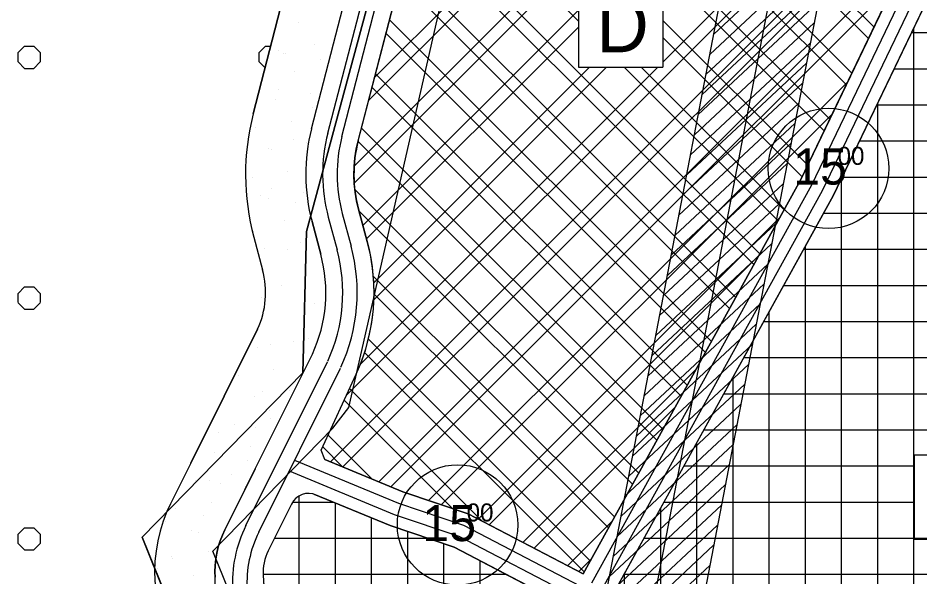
# Model space of a CAD drawing. Extents: x 419109 to 421295, y 4452223 to 4457798.
# Drawn here: x 419705 to 420079.2, y 4455575.7 to 4455807.8 of the extents above; entities that cross this region are included whole.
import ezdxf

# ---------------------------------------------------------------- set-up
doc = ezdxf.new("R2010")
doc.units = 0
for name, color, linetype in [('ADA', 7, 'Continuous'), ('ADAKENARI', 7, 'Continuous'), ('KALDIRIM_FAT', 7, 'Continuous'), ('KD_DAIRE', 7, 'Continuous'), ('KD_YGEN', 7, 'Continuous'), ('PL_AYA_PARK_DINLENME', 7, 'Continuous'), ('PL_K_DEPOLAMA', 7, 'Continuous'), ('PL_KA_TARIM_ALANI', 7, 'Continuous'), ('PL_TİCARET', 7, 'Continuous'), ('SEMBOL_FAT', 7, 'Continuous'), ('TA_ENH_154', 7, 'Continuous'), ('TA_ENH_KORUMA', 7, 'Continuous'), ('TA_ENH_TARAMA', 7, 'Continuous'), ('TR_TARIMALANI', 7, 'Continuous'), ('TRFAT_DEPOLAMA', 7, 'Continuous'), ('TRFAT_PARKALANI', 7, 'Continuous'), ('TRFAT_TİCARET', 7, 'Continuous')]:
    doc.layers.add(name, color=color, linetype=linetype)

msp = doc.modelspace()

# ---------------------------------------------------------------- linework, layer by layer
at = {"layer": 'ADA'}
for p, q in [((419756.46, 4455592.19), (419823.13, 4455660.45)), ((419783.44, 4455525.52), (419756.46, 4455592.19))]:
    msp.add_line(p, q, dxfattribs=at)
at = {"layer": 'ADAKENARI'}
for p, q in [((419802.57, 4455768.04), (419857.93, 4455982.18)), ((419826.78, 4455761.78), (419882.14, 4455975.93)), ((419846.14, 4455756.78), (419902.93, 4455976.43)), ((420043.17, 4455733.9), (420134.21, 4455923.79)), ((420029.83, 4455740.78), (420113.83, 4455915.99)), ((419939.44, 4455577), (420029.83, 4455740.78)), ((419945.46, 4455556.86), (420043.17, 4455733.9)), ((419846.28, 4455728.45), (419849.92, 4455714.93)), ((419826.97, 4455723.26), (419830.61, 4455709.74)), ((419802.83, 4455716.76), (419806.46, 4455703.24)), ((419776.71, 4455623), (419804.4, 4455678.61)), ((419803.43, 4455620.54), (419827.12, 4455668.19)), ((419830.81, 4455628.27), (419845.3, 4455659.85)), ((419832.33, 4455624.4), (419830.81, 4455628.27)), ((419776.71, 4455623), (419768.21, 4455605.99)), ((419832.33, 4455624.4), (419864.61, 4455611.04)), ((419803.43, 4455620.54), (419799.07, 4455611.82)), ((419799.07, 4455611.82), (419790.75, 4455595.18)), ((419864.61, 4455611.04), (419891.81, 4455601.83)), ((419819.29, 4455607.23), (419818.5, 4455605.96)), ((419820.3, 4455608.33), (419819.29, 4455607.23)), ((419821.51, 4455609.22), (419820.3, 4455608.33)), ((419822.85, 4455609.88), (419821.51, 4455609.22)), ((419824.3, 4455610.27), (419822.85, 4455609.88)), ((419825.79, 4455610.38), (419824.3, 4455610.27)), ((419827.28, 4455610.21), (419825.79, 4455610.38)), ((419827.67, 4455610.1), (419827.28, 4455610.21)), ((419827.67, 4455610.1), (419859.33, 4455596.99)), ((419768.21, 4455605.99), (419766.74, 4455602.8)), ((419818.5, 4455605.96), (419808.79, 4455586.53)), ((419766.74, 4455602.8), (419765.22, 4455598.83)), ((419891.81, 4455601.83), (419939.44, 4455577)), ((419765.22, 4455598.83), (419763.96, 4455594.76)), ((419859.33, 4455596.99), (419885.9, 4455587.99)), ((419763.96, 4455594.76), (419762.97, 4455590.63)), ((419789.8, 4455593.1), (419788.86, 4455590.66)), ((419790.75, 4455595.18), (419789.8, 4455593.1)), ((419762.97, 4455590.63), (419762.26, 4455586.44)), ((419762.84, 4455589.82), (419762.4, 4455587.24)), ((419788.86, 4455590.66), (419788.09, 4455588.16)), ((419762.26, 4455586.44), (419761.82, 4455582.21)), ((419787.48, 4455585.61), (419787.04, 4455583.03)), ((419788.09, 4455588.16), (419787.48, 4455585.61)), ((419808.24, 4455585.34), (419807.77, 4455584.12)), ((419808.79, 4455586.53), (419808.24, 4455585.34)), ((419885.9, 4455587.99), (419940.17, 4455559.7)), ((419761.82, 4455582.21), (419761.65, 4455577.95)), ((419787.04, 4455583.03), (419786.77, 4455580.43)), ((419807.08, 4455581.6), (419806.86, 4455580.31)), ((419807.39, 4455582.87), (419807.08, 4455581.6)), ((419807.77, 4455584.12), (419807.39, 4455582.87)), ((419761.65, 4455577.95), (419761.75, 4455574.44)), ((419786.77, 4455580.43), (419786.67, 4455577.82)), ((419786.67, 4455577.82), (419786.73, 4455575.53)), ((419806.73, 4455579.01), (419806.68, 4455577.7)), ((419806.68, 4455577.7), (419806.71, 4455576.4)), ((419806.86, 4455580.31), (419806.73, 4455579.01)), ((419806.71, 4455576.4), (419815.93, 4455422.24))]:
    msp.add_line(p, q, dxfattribs=at)
for centre, radius, start, end in [((419899.91, 4455742.88), 100.53, 165.5054, 195.0581), ((419899.91, 4455742.88), 75.53, 165.5054, 195.0581), ((419899.91, 4455742.88), 55.53, 165.5054, 195.0581), ((419771.33, 4455693.79), 81.39, 335.3525, 15.0581), ((419771.33, 4455693.79), 61.39, 335.3525, 15.0581), ((419771.33, 4455693.79), 36.39, 335.3525, 15.0581)]:
    msp.add_arc(centre, radius, start, end, dxfattribs=at)
at = {"layer": 'KALDIRIM_FAT'}
for p, q in [((419833.56, 4455760.03), (419888.92, 4455974.18)), ((419839.36, 4455758.53), (419894.72, 4455972.67)), ((420034.28, 4455738.49), (420119.46, 4455916.16)), ((420038.73, 4455736.19), (420123.97, 4455914)), ((419943.11, 4455573.29), (420034.28, 4455738.49)), ((419947.48, 4455570.88), (420038.73, 4455736.19)), ((419833.73, 4455725.07), (419837.36, 4455711.56)), ((419839.52, 4455726.63), (419843.16, 4455713.11)), ((419799.53, 4455596.98), (419833.39, 4455665.07)), ((419804.9, 4455594.31), (419838.76, 4455662.4)), ((419819.76, 4455624.19), (419862.85, 4455606.36)), ((419817.53, 4455619.7), (419861.09, 4455601.68)), ((419862.85, 4455606.36), (419889.84, 4455597.22)), ((419861.09, 4455601.68), (419887.87, 4455592.6)), ((419889.84, 4455597.22), (419938.43, 4455571.88)), ((419887.87, 4455592.6), (419936.12, 4455567.45))]:
    msp.add_line(p, q, dxfattribs=at)
for centre, radius, start, end in [((419899.91, 4455742.88), 68.53, 165.5054, 195.0581), ((419899.91, 4455742.88), 62.53, 165.5054, 195.0581), ((419771.33, 4455693.79), 74.39, 335.3525, 15.0581), ((419771.33, 4455693.79), 68.39, 335.3525, 15.0581), ((419847.11, 4455573.32), 53.14, 153.5603, 183.4213), ((419847.11, 4455573.32), 47.14, 153.5603, 183.4213)]:
    msp.add_arc(centre, radius, start, end, dxfattribs=at)
at = {"layer": 'KD_DAIRE'}
for centre in [(420041.27, 4455745.36), (419887.38, 4455597.27)]:
    msp.add_circle(centre, 25, dxfattribs=at)
at = {"layer": 'PL_AYA_PARK_DINLENME'}
for p, q in [((419857.93, 4455982.18), (419802.57, 4455768.04)), ((419826.78, 4455761.78), (419882.14, 4455975.93)), ((419830.6, 4455709.74), (419826.97, 4455723.26)), ((419802.83, 4455716.76), (419806.46, 4455703.24)), ((419806.46, 4455703.24), (419806.46, 4455703.24))]:
    msp.add_line(p, q, dxfattribs=at)
for points in [[(420016.8, 4456927.25), (420013.63, 4456854.22), (420021.56, 4456763.74), (419972.35, 4456528.79), (419896.15, 4456444.66), (419851.71, 4456390.68), (419781.86, 4456219.24), (419743.76, 4456181.14), (419715.18, 4456046.21), (419900.92, 4456001.76), (419824.72, 4455719.19), (419823.13, 4455660.45), (419756.46, 4455592.19), (419783.44, 4455525.52), (419794.56, 4455425.51), (419778.68, 4455323.91)], [(419804.18, 4455325.18), (419819.77, 4455424.95), (419807.91, 4455531.7), (419785.76, 4455586.42), (419835.59, 4455637.43), (419842.19, 4455646.09), (419927.54, 4456021.09), (419744.69, 4456064.85), (419766.68, 4456168.71), (419803.1, 4456205.13), (419873.42, 4456377.73), (419915.08, 4456428.31), (419995.43, 4456517.04), (420046.79, 4456762.24), (420038.67, 4456854.78), (420041.73, 4456924.97)], [(419804.4, 4455678.61), (419776.71, 4455623), (419768.21, 4455605.99), (419766.74, 4455602.8), (419765.22, 4455598.83), (419763.96, 4455594.76), (419762.97, 4455590.63), (419762.84, 4455589.82), (419762.4, 4455587.24), (419762.26, 4455586.44), (419761.82, 4455582.21), (419761.65, 4455577.95), (419761.75, 4455574.44), (419762.54, 4455561.28), (419771.07, 4455418.55), (419772.93, 4455400.8), (419770.22, 4455288.15), (419798.46, 4455144.95), (419791.07, 4455126.52), (419788.42, 4455109.34), (419786.36, 4455074.3), (419779.83, 4455031.69), (419779.71, 4455015.11)], [(419795.28, 4455290.29), (419797.57, 4455385.64), (419797.88, 4455390.78), (419798.11, 4455400.41), (419795.99, 4455420.6), (419787.49, 4455562.77), (419786.85, 4455573.45), (419786.73, 4455575.53), (419786.67, 4455577.82), (419786.77, 4455580.43), (419787.04, 4455583.03), (419787.48, 4455585.61), (419788.09, 4455588.16), (419788.86, 4455590.66), (419789.8, 4455593.1), (419790.75, 4455595.18), (419799.07, 4455611.82), (419803.43, 4455620.54), (419827.12, 4455668.19)]]:
    msp.add_lwpolyline(points, dxfattribs=at)
for centre, radius, start, end in [((419899.91, 4455742.88), 100.53, 165.5054, 195.0581), ((419899.91, 4455742.88), 75.53, 165.5054, 195.0581), ((419771.33, 4455693.79), 61.39, 335.3525, 15.0581), ((419771.33, 4455693.79), 36.39, 335.3525, 15.0573), ((419771.33, 4455693.79), 36.39, 15.0575, 15.0581)]:
    msp.add_arc(centre, radius, start, end, dxfattribs=at)
at = {"layer": 'PL_K_DEPOLAMA'}
msp.add_lwpolyline([(420113.83, 4455915.99), (420029.83, 4455740.78), (419939.44, 4455577), (419891.81, 4455601.83), (419864.61, 4455611.04), (419832.33, 4455624.4), (419830.81, 4455628.27), (419845.3, 4455659.85), (419847.47, 4455665.05), (419849.28, 4455670.39), (419850.71, 4455675.85), (419851.76, 4455681.39), (419852.43, 4455686.99), (419852.7, 4455692.62), (419852.59, 4455698.26), (419852.09, 4455703.87), (419851.19, 4455709.44), (419849.92, 4455714.93), (419846.28, 4455728.45), (419845.46, 4455731.94), (419844.87, 4455735.47), (419844.51, 4455739.03), (419844.38, 4455742.61), (419844.47, 4455746.18), (419844.8, 4455749.75), (419845.36, 4455753.28), (419846.14, 4455756.78), (419846.14, 4455756.78), (419902.93, 4455976.43)], dxfattribs=at)
at = {"layer": 'PL_KA_TARIM_ALANI'}
msp.add_lwpolyline([(419792.54, 4455014.98), (419819.96, 4455165.16), (419778.68, 4455323.91), (419794.56, 4455425.51), (419783.44, 4455525.52), (419756.46, 4455592.19), (419823.13, 4455660.45), (419824.72, 4455719.19), (419900.92, 4456001.76), (419869.84, 4456009.19), (419715.18, 4456046.21), (419743.76, 4456181.14), (419781.86, 4456219.24), (419851.71, 4456390.68), (419896.15, 4456444.66), (419972.35, 4456528.79), (420021.56, 4456763.74), (420013.63, 4456854.22), (420016.8, 4456927.25), (420027.91, 4457006.62), (420158.52, 4456994.43), (420142.12, 4457086.4)], dxfattribs=at)
at = {"layer": 'PL_TİCARET'}
for points in [[(420153.07, 4455976.48), (420152.11, 4455974.16), (420151.45, 4455961.22), (420137.18, 4455930.24), (420134.21, 4455923.79), (420043.17, 4455733.9), (419945.46, 4455556.86), (419940.17, 4455559.7)], [(419940.17, 4455559.7), (419885.9, 4455587.99), (419859.33, 4455596.99), (419827.67, 4455610.1), (419827.28, 4455610.21), (419825.79, 4455610.38), (419824.3, 4455610.27), (419822.85, 4455609.88), (419821.51, 4455609.22), (419820.3, 4455608.33), (419819.29, 4455607.23), (419818.5, 4455605.96), (419808.79, 4455586.53), (419808.24, 4455585.34), (419807.77, 4455584.12), (419807.39, 4455582.87), (419807.08, 4455581.6), (419806.86, 4455580.31), (419806.73, 4455579.01), (419806.68, 4455577.7), (419806.71, 4455576.4), (419815.93, 4455422.24)]]:
    msp.add_lwpolyline(points, dxfattribs=at)
at = {"layer": 'SEMBOL_FAT'}
for p, q in [((419937.51, 4455822.43), (419937.51, 4455787.43)), ((419972.51, 4455822.43), (419972.51, 4455787.43)), ((419937.51, 4455787.43), (419972.51, 4455787.43)), ((420076.85, 4455626.43), (420076.85, 4455591.43)), ((420076.85, 4455626.43), (420111.85, 4455626.43)), ((420076.85, 4455591.43), (420111.85, 4455591.43))]:
    msp.add_line(p, q, dxfattribs=at)
at = {"layer": 'TA_ENH_154'}
msp.add_lwpolyline([(419862.83, 4455014.24), (420170.14, 4456613.6), (420230.68, 4456928.68), (420176.89, 4457440.84), (420133.44, 4457787.81)], dxfattribs=at)
at = {"layer": 'TA_ENH_KORUMA'}
msp.add_line((419842.5, 4455014.45), (420150.5, 4456617.38), dxfattribs=at)
msp.add_lwpolyline([(420153.62, 4457787.6), (420196.76, 4457443.12), (420250.88, 4456927.82), (420189.78, 4456609.83), (419883.15, 4455014.02)], dxfattribs=at)
at = {"layer": 'TA_ENH_TARAMA'}
for p, q in [((419993.64, 4455801.05), (420043.29, 4455847.45)), ((419992.04, 4455792.71), (420041.69, 4455839.11)), ((419990.43, 4455784.37), (420040.08, 4455830.77)), ((419988.83, 4455776.02), (420038.48, 4455822.42)), ((419987.23, 4455767.68), (420036.88, 4455814.08)), ((419985.62, 4455759.34), (420035.28, 4455805.74)), ((419984.02, 4455751), (420033.67, 4455797.4)), ((419982.42, 4455742.65), (420032.07, 4455789.06)), ((419980.82, 4455734.31), (420030.47, 4455780.71)), ((419979.21, 4455725.97), (420028.86, 4455772.37)), ((419977.61, 4455717.63), (420027.26, 4455764.03)), ((419976.01, 4455709.28), (420025.66, 4455755.69)), ((419974.4, 4455700.94), (420024.06, 4455747.34)), ((419972.8, 4455692.6), (420022.45, 4455739)), ((419971.2, 4455684.26), (420020.85, 4455730.66)), ((419969.59, 4455675.92), (420019.25, 4455722.32)), ((419967.99, 4455667.57), (420017.64, 4455713.98)), ((419966.39, 4455659.23), (420016.04, 4455705.63)), ((419964.79, 4455650.89), (420014.44, 4455697.29)), ((419963.18, 4455642.55), (420012.83, 4455688.95)), ((419961.58, 4455634.2), (420011.23, 4455680.61)), ((419959.98, 4455625.86), (420009.63, 4455672.26)), ((419958.37, 4455617.52), (420008.03, 4455663.92)), ((419956.77, 4455609.18), (420006.42, 4455655.58)), ((419955.17, 4455600.84), (420004.82, 4455647.24)), ((419953.57, 4455592.49), (420003.22, 4455638.9)), ((419951.96, 4455584.15), (420001.61, 4455630.55)), ((419950.36, 4455575.81), (420000.01, 4455622.21)), ((419948.76, 4455567.47), (419998.41, 4455613.87)), ((419947.15, 4455559.12), (419996.81, 4455605.53)), ((419945.55, 4455550.78), (419995.2, 4455597.18)), ((419943.95, 4455542.44), (419993.6, 4455588.84)), ((419942.35, 4455534.1), (419992, 4455580.5))]:
    msp.add_line(p, q, dxfattribs=at)
at = {"layer": 'TR_TARIMALANI'}
for p, q in [((419705, 4455793.42), (419707.71, 4455796.13)), ((419707.75, 4455796.14), (419711.58, 4455796.14)), ((419714.25, 4455793.42), (419711.54, 4455796.13)), ((419805, 4455793.42), (419807.71, 4455796.13)), ((419807.74, 4455796.14), (419809.84, 4455796.14)), ((419705.04, 4455789.6), (419705.04, 4455793.43)), ((419714.29, 4455789.6), (419714.29, 4455793.43)), ((419805.03, 4455789.6), (419805.03, 4455793.43)), ((419707.71, 4455786.88), (419705, 4455789.59)), ((419707.75, 4455786.89), (419711.58, 4455786.89)), ((419711.54, 4455786.88), (419714.25, 4455789.59)), ((419807.5, 4455787.09), (419805, 4455789.59)), ((419705, 4455693.42), (419707.71, 4455696.13)), ((419705.04, 4455689.6), (419705.04, 4455693.43)), ((419707.75, 4455696.14), (419711.58, 4455696.14)), ((419714.25, 4455693.42), (419711.54, 4455696.13)), ((419714.29, 4455689.6), (419714.29, 4455693.43)), ((419707.71, 4455686.88), (419705, 4455689.59)), ((419711.54, 4455686.88), (419714.25, 4455689.59)), ((419707.75, 4455686.89), (419711.58, 4455686.89)), ((419705, 4455593.42), (419707.71, 4455596.13)), ((419707.75, 4455596.14), (419711.58, 4455596.14)), ((419714.25, 4455593.42), (419711.54, 4455596.13)), ((419705.04, 4455589.6), (419705.04, 4455593.43)), ((419714.29, 4455589.6), (419714.29, 4455593.43)), ((419707.71, 4455586.88), (419705, 4455589.59)), ((419711.54, 4455586.88), (419714.25, 4455589.59)), ((419707.75, 4455586.89), (419711.58, 4455586.89))]:
    msp.add_line(p, q, dxfattribs=at)
at = {"layer": 'TRFAT_DEPOLAMA'}
for p, q in [((419899.81, 4455964.36), (420060.15, 4455804.01)), ((419898.35, 4455958.74), (420057.86, 4455799.23)), ((419850.47, 4455773.54), (420028.3, 4455951.36)), ((419852.94, 4455783.07), (420023.29, 4455953.43)), ((419844.49, 4455746.34), (420043.3, 4455945.15)), ((419844.5, 4455739.28), (420048.31, 4455943.08)), ((419894, 4455941.88), (420050.99, 4455784.89)), ((419892.54, 4455936.27), (420048.69, 4455780.11)), ((419841.38, 4455651.3), (420108.34, 4455918.26)), ((419888.19, 4455919.41), (420041.82, 4455765.78)), ((419972.51, 4455789.51), (420103.33, 4455920.33)), ((419886.73, 4455913.79), (420039.53, 4455761)), ((419834.7, 4455623.42), (420101.45, 4455890.16)), ((419839.71, 4455621.35), (420094.94, 4455876.58)), ((419875.11, 4455868.84), (419937.51, 4455806.44)), ((419870.76, 4455851.99), (420012.81, 4455709.93)), ((419869.3, 4455846.37), (420010.3, 4455705.38)), ((419854.71, 4455615.14), (420075.41, 4455835.83)), ((419864.95, 4455829.51), (420002.75, 4455691.71)), ((419859.71, 4455613.07), (420068.89, 4455822.25)), ((419863.49, 4455823.89), (420000.24, 4455687.15)), ((419848.11, 4455721.67), (419937.51, 4455811.08)), ((419859.14, 4455807.04), (419992.69, 4455673.48)), ((419972.51, 4455806.8), (420032.65, 4455746.66)), ((419849.6, 4455716.1), (419937.51, 4455804.01)), ((419857.68, 4455801.42), (419990.18, 4455668.93)), ((419972.51, 4455799.73), (420030.36, 4455741.88)), ((419847.05, 4455664.05), (419970.43, 4455787.43)), ((419852.6, 4455697.88), (419942.15, 4455787.43)), ((419852.62, 4455690.83), (419949.22, 4455787.43)), ((419956.53, 4455787.43), (420020.36, 4455723.6)), ((419963.6, 4455787.43), (420022.87, 4455728.16)), ((419853.33, 4455784.56), (419982.63, 4455655.26)), ((419875.28, 4455607.43), (420049.36, 4455781.5)), ((419851.87, 4455778.95), (419980.12, 4455650.7)), ((419880.57, 4455605.64), (420042.85, 4455767.92)), ((419847.52, 4455762.09), (419972.57, 4455637.03)), ((419846.07, 4455756.46), (419970.06, 4455632.47)), ((419844.76, 4455736.56), (419962.52, 4455618.81)), ((419846.46, 4455727.79), (419960, 4455614.25)), ((419895.86, 4455599.72), (420021.11, 4455724.97)), ((419900.51, 4455597.29), (420012.4, 4455709.19)), ((419852.37, 4455700.66), (419952.46, 4455600.58)), ((419852.69, 4455693.28), (419949.94, 4455596.02)), ((419850.34, 4455674.42), (419942.4, 4455582.36)), ((419848.77, 4455668.91), (419939.88, 4455577.8)), ((419914.45, 4455590.02), (419986.27, 4455661.84)), ((419842.57, 4455653.9), (419897.72, 4455598.74)), ((419840.34, 4455649.05), (419885.4, 4455604)), ((419919.1, 4455587.6), (419977.56, 4455646.06)), ((419833.67, 4455634.51), (419851.87, 4455616.31)), ((419831.45, 4455629.66), (419839.81, 4455621.3)), ((419933.04, 4455580.33), (419951.43, 4455598.72)), ((419937.69, 4455577.91), (419942.72, 4455582.94))]:
    msp.add_line(p, q, dxfattribs=at)
at = {"layer": 'TRFAT_PARKALANI'}
for p, q in [((419821.21, 4455805.96), (419821.21, 4455805.96)), ((419813.1, 4455794.38), (419813.1, 4455794.38)), ((419827.87, 4455796.98), (419827.87, 4455796.98)), ((419815.19, 4455793.16), (419815.19, 4455793.16)), ((419815.84, 4455793.06), (419815.84, 4455793.06)), ((419830.61, 4455790.45), (419830.61, 4455790.45)), ((419819.76, 4455785.4), (419819.76, 4455785.4)), ((419813.24, 4455778.29), (419813.24, 4455778.29)), ((419826.42, 4455776.42), (419826.42, 4455776.42)), ((419811.65, 4455773.81), (419811.65, 4455773.81)), ((419827.14, 4455770.76), (419827.14, 4455770.76)), ((419818.31, 4455764.83), (419818.31, 4455764.83)), ((419803.54, 4455762.23), (419803.54, 4455762.23)), ((419819.16, 4455757.32), (419819.16, 4455757.32)), ((419808.89, 4455753.67), (419808.89, 4455753.67)), ((419810.2, 4455753.25), (419810.2, 4455753.25)), ((419824.53, 4455755.98), (419824.53, 4455755.98)), ((419824.97, 4455755.85), (419824.97, 4455755.85)), ((419816.86, 4455744.27), (419816.86, 4455744.27)), ((419802.09, 4455741.66), (419802.09, 4455741.66)), ((419810.26, 4455736.8), (419810.26, 4455736.8)), ((419823.52, 4455735.29), (419823.52, 4455735.29)), ((419805.42, 4455733.97), (419805.42, 4455733.97)), ((419808.75, 4455732.69), (419808.75, 4455732.69)), ((419820.19, 4455731.36), (419820.19, 4455731.36)), ((419815.41, 4455723.71), (419815.41, 4455723.71)), ((419802.82, 4455719.2), (419802.82, 4455719.2)), ((419807.3, 4455712.12), (419807.3, 4455712.12)), ((419822.07, 4455714.73), (419822.07, 4455714.73)), ((419816.72, 4455711.67), (419816.72, 4455711.67)), ((419814.12, 4455696.9), (419814.12, 4455696.9)), ((419805.85, 4455691.56), (419805.85, 4455691.56)), ((419828.02, 4455689.37), (419828.02, 4455689.37)), ((419825.42, 4455674.6), (419825.42, 4455674.6)), ((419804.4, 4455670.99), (419804.4, 4455670.99)), ((419809.77, 4455672.28), (419809.77, 4455672.28)), ((419819.17, 4455673.6), (419819.17, 4455673.6)), ((419796.28, 4455659.41), (419796.28, 4455659.41)), ((419811.06, 4455662.01), (419811.06, 4455662.01)), ((419806.3, 4455652.58), (419806.3, 4455652.58)), ((419817.72, 4455653.03), (419817.72, 4455653.03)), ((419802.95, 4455650.43), (419802.95, 4455650.43)), ((419809.29, 4455644.61), (419809.29, 4455644.61)), ((419809.61, 4455641.45), (419809.61, 4455641.45)), ((419794.83, 4455638.84), (419794.83, 4455638.84)), ((419803.7, 4455637.81), (419803.7, 4455637.81)), ((419788.06, 4455635.49), (419788.06, 4455635.49)), ((419801.49, 4455629.86), (419801.49, 4455629.86)), ((419786.72, 4455627.26), (419786.72, 4455627.26)), ((419800.4, 4455624.1), (419800.4, 4455624.1)), ((419793.38, 4455618.28), (419793.38, 4455618.28)), ((419778.61, 4455615.67), (419778.61, 4455615.67)), ((419784.58, 4455615.79), (419784.58, 4455615.79)), ((419788.91, 4455614.45), (419788.91, 4455614.45)), ((419799.36, 4455613.19), (419799.36, 4455613.19)), ((419770.5, 4455604.09), (419770.5, 4455604.09)), ((419785.27, 4455606.69), (419785.27, 4455606.69)), ((419781.98, 4455601.02), (419781.98, 4455601.02)), ((419766.34, 4455598.7), (419766.34, 4455598.7)), ((419791.93, 4455597.71), (419791.93, 4455597.71)), ((419777.16, 4455595.11), (419777.16, 4455595.11)), ((419780.02, 4455593.94), (419780.02, 4455593.94)), ((419783.82, 4455586.13), (419783.82, 4455586.13)), ((419768.53, 4455584.3), (419768.53, 4455584.3)), ((419769.05, 4455583.52), (419769.05, 4455583.52)), ((419762.87, 4455579), (419762.87, 4455579)), ((419777.64, 4455576.4), (419777.64, 4455576.4))]:
    msp.add_line(p, q, dxfattribs=at)
at = {"layer": 'TRFAT_TİCARET'}
for p, q in [((420075.71, 4455801.77), (420224.89, 4455801.77)), ((420076.68, 4455202.54), (420076.68, 4455803.79)), ((420068.52, 4455786.77), (420223.98, 4455786.77)), ((420061.33, 4455771.77), (420223.07, 4455771.77)), ((420061.68, 4455185.7), (420061.68, 4455772.5)), ((420054.14, 4455756.77), (420222.22, 4455756.77)), ((420046.95, 4455741.77), (420221.38, 4455741.77)), ((420046.68, 4455173.41), (420046.68, 4455741.21)), ((420039.24, 4455726.77), (420220.53, 4455726.77)), ((420030.96, 4455711.77), (420219.69, 4455711.77)), ((420031.68, 4455161.13), (420031.68, 4455713.07)), ((420022.68, 4455696.77), (420218.84, 4455696.77)), ((420016.68, 4455148.86), (420016.68, 4455685.9)), ((420014.4, 4455681.77), (420218, 4455681.77)), ((420006.12, 4455666.77), (420217.15, 4455666.77)), ((420001.68, 4455136.59), (420001.68, 4455658.72)), ((419997.85, 4455651.77), (420216.31, 4455651.77)), ((419989.57, 4455636.77), (420215.47, 4455636.77)), ((419986.68, 4455124.32), (419986.68, 4455631.54)), ((419981.29, 4455621.77), (420076.85, 4455621.77)), ((419821.68, 4455259.79), (419821.68, 4455609.31)), ((419819.01, 4455606.77), (419835.69, 4455606.77)), ((419836.68, 4455183.73), (419836.68, 4455606.37)), ((419971.68, 4455112.05), (419971.68, 4455604.36)), ((419973.01, 4455606.77), (420076.85, 4455606.77)), ((419851.68, 4455183.32), (419851.68, 4455600.16)), ((419866.68, 4455183.91), (419866.68, 4455594.51)), ((419811.41, 4455591.77), (419874.74, 4455591.77)), ((419881.68, 4455184.49), (419881.68, 4455589.42)), ((419964.73, 4455591.77), (420213.06, 4455591.77)), ((419896.68, 4455185.08), (419896.68, 4455582.37)), ((419956.68, 4455127.52), (419956.68, 4455577.19)), ((419806.7, 4455576.77), (419907.42, 4455576.77)), ((419956.45, 4455576.77), (420212.31, 4455576.77))]:
    msp.add_line(p, q, dxfattribs=at)

# ---------------------------------------------------------------- texts
at = {"layer": 'KD_YGEN'}
for s, height, p in [('15', 15, (420026.61, 4455738.66)), ('00', 7.5, (420045.02, 4455746.81)), ('15', 15, (419872.72, 4455590.57)), ('00', 7.5, (419891.12, 4455598.72))]:
    msp.add_text(s, height=height, dxfattribs=at).set_placement(p)
at = {"layer": 'SEMBOL_FAT'}
msp.add_text('D', height=22.5, dxfattribs=at).set_placement((419944.96, 4455793.59))

doc.saveas('drawing.dxf')
